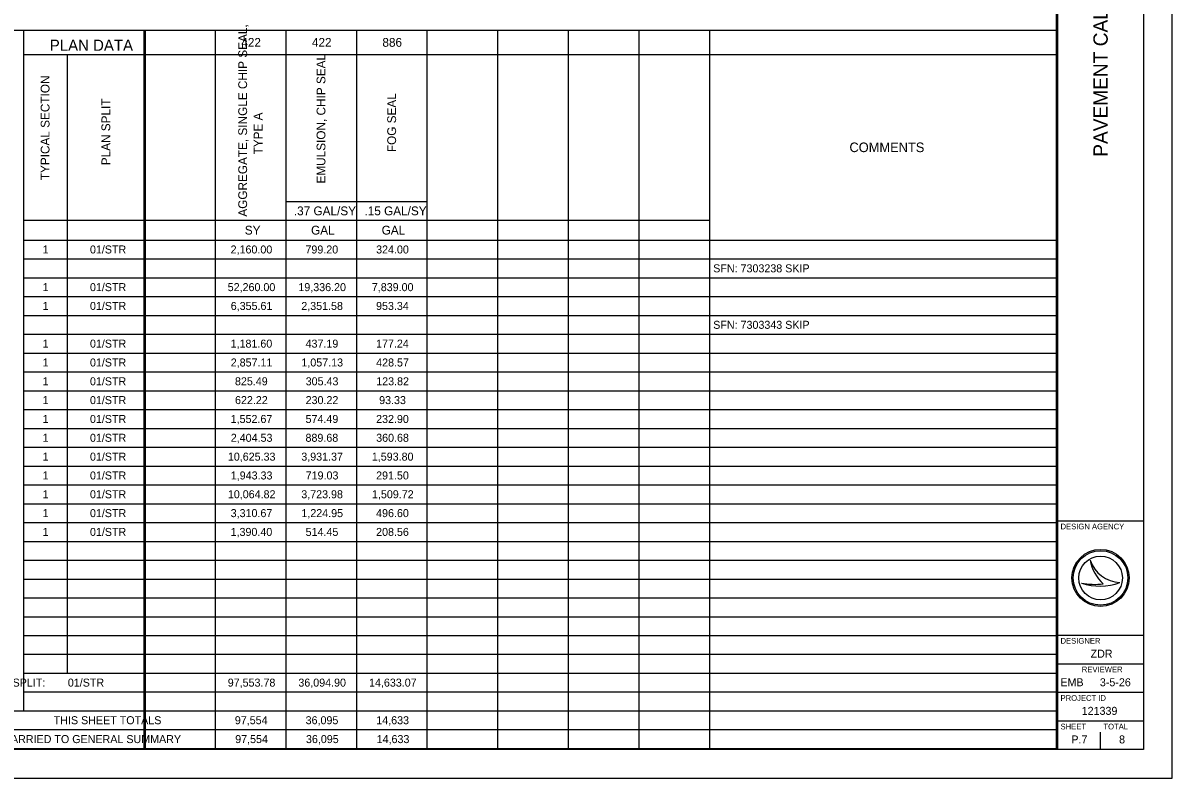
# Model space of a CAD drawing. Extents: x 0 to 34, y 0 to 31.9.
# Drawn here: x 13.9 to 34, y 0 to 13.21 of the extents above; entities that cross this region are included whole.
import ezdxf

# ---------------------------------------------------------------- set-up
doc = ezdxf.new("R2010")
doc.units = 0
for name, color, linetype in [('SH_Border', 7, 'Continuous'), ('SH_Cut_Line', 7, 'Continuous'), ('SH_Data', 7, 'Continuous'), ('SH_Text', 7, 'Continuous')]:
    doc.layers.add(name, color=color, linetype=linetype)

msp = doc.modelspace()

# ---------------------------------------------------------------- linework, layer by layer
at = {"layer": 'SH_Border'}
for p, q in [((32, 0.5), (32, 21.5)), ((32, 4.5), (33.5, 4.5)), ((32, 2.5), (33.5, 2.5)), ((32, 2), (33.5, 2)), ((32, 1.5), (33.5, 1.5)), ((32, 1), (33.5, 1))]:
    msp.add_line(p, q, dxfattribs=at)
msp.add_lwpolyline([(1.5, 21.5), (33.5, 21.5), (33.5, 0.5), (1.5, 0.5)], close=True, dxfattribs=at)
at = {"layer": 'SH_Cut_Line'}
msp.add_lwpolyline([(0, 0), (34, 0), (34, 22), (0, 22)], close=True, dxfattribs=at)
at = {"layer": 'SH_Data'}
for p, q in [((32.567, 3.81), (32.567, 3.81)), ((32.75, 3.5), (32.75, 3.5)), ((33.087, 3.419), (33.087, 3.419)), ((32.417, 3.41), (32.417, 3.41)), ((32.375, 0.675), (32.375, 0.675)), ((32.75, 0.5), (32.75, 0.8))]:
    msp.add_line(p, q, dxfattribs=at)
for radius in [0.5, 0.477, 0.477, 0.382]:
    msp.add_circle((32.75, 3.5), radius, dxfattribs=at)
for centre, radius, start, end in [((33.116, 3.998), 0.58, 198.9257, 198.9319), ((33.347, 3.97), 0.796, 191.6379, 191.6421), ((33.116, 3.998), 0.58, 198.9319, 267.1657), ((33.347, 3.97), 0.796, 191.6421, 226.0947), ((32.739, 4.37), 1.013, 251.4576, 290.0832), ((32.648, 4.654), 1.266, 259.4964, 259.4995), ((32.739, 4.37), 1.013, 251.4527, 251.4576), ((32.648, 4.654), 1.266, 259.4995, 276.6672)]:
    msp.add_arc(centre, radius, start, end, dxfattribs=at)
at = {"layer": 'SH_Text'}
for p, q in [((31.971, 21.5), (31.971, 0.516)), ((9.065, 13.084), (13.913, 13.084)), ((13.891, 13.084), (16.038, 13.084)), ((13.913, 13.084), (13.913, 1.175)), ((16.016, 13.084), (31.971, 13.084)), ((16.016, 13.084), (16.016, 0.516)), ((16.038, 13.084), (16.038, 0.516)), ((17.262, 13.084), (17.262, 0.516)), ((18.498, 13.084), (18.498, 0.516)), ((19.733, 13.084), (19.733, 0.516)), ((20.968, 13.084), (20.968, 0.516)), ((22.204, 13.084), (22.204, 0.516)), ((23.439, 13.084), (23.439, 0.516)), ((24.674, 13.084), (24.674, 0.516)), ((25.909, 13.084), (25.909, 0.516)), ((13.913, 12.655), (16.016, 12.655)), ((14.676, 12.655), (14.676, 1.834)), ((16.038, 12.655), (31.971, 12.655)), ((18.498, 10.086), (20.968, 10.086)), ((13.913, 9.756), (16.016, 9.756)), ((16.038, 9.756), (25.909, 9.756)), ((13.913, 9.411), (16.016, 9.411)), ((16.038, 9.411), (31.971, 9.411)), ((13.913, 9.081), (16.016, 9.081)), ((16.038, 9.081), (31.971, 9.081)), ((13.913, 8.752), (16.016, 8.752)), ((16.038, 8.752), (31.971, 8.752)), ((13.913, 8.422), (16.016, 8.422)), ((16.038, 8.422), (31.971, 8.422)), ((13.913, 8.093), (16.016, 8.093)), ((16.038, 8.093), (31.971, 8.093)), ((13.913, 7.764), (16.016, 7.764)), ((16.038, 7.764), (31.971, 7.764)), ((13.913, 7.434), (16.016, 7.434)), ((16.038, 7.434), (31.971, 7.434)), ((13.913, 7.105), (16.016, 7.105)), ((16.038, 7.105), (31.971, 7.105)), ((13.913, 6.775), (16.016, 6.775)), ((16.038, 6.775), (31.971, 6.775)), ((13.913, 6.446), (16.016, 6.446)), ((16.038, 6.446), (31.971, 6.446)), ((13.913, 6.116), (16.016, 6.116)), ((16.038, 6.116), (31.971, 6.116)), ((13.913, 5.787), (16.016, 5.787)), ((16.038, 5.787), (31.971, 5.787)), ((13.913, 5.458), (16.016, 5.458)), ((16.038, 5.458), (31.971, 5.458)), ((13.913, 5.128), (16.016, 5.128)), ((16.038, 5.128), (31.971, 5.128)), ((13.913, 4.799), (16.016, 4.799)), ((16.038, 4.799), (31.971, 4.799)), ((13.913, 4.469), (16.016, 4.469)), ((16.038, 4.469), (31.971, 4.469)), ((13.913, 4.14), (16.016, 4.14)), ((16.038, 4.14), (31.971, 4.14)), ((13.913, 3.811), (16.016, 3.811)), ((16.038, 3.811), (31.971, 3.811)), ((13.913, 3.481), (16.016, 3.481)), ((16.038, 3.481), (31.971, 3.481)), ((13.913, 3.152), (16.016, 3.152)), ((16.038, 3.152), (31.971, 3.152)), ((13.913, 2.822), (16.016, 2.822)), ((16.038, 2.822), (31.971, 2.822)), ((13.913, 2.493), (16.016, 2.493)), ((16.038, 2.493), (31.971, 2.493)), ((13.913, 2.164), (16.016, 2.164)), ((16.038, 2.164), (31.971, 2.164)), ((13.913, 1.834), (16.016, 1.834)), ((16.038, 1.834), (31.971, 1.834)), ((13.913, 1.505), (16.016, 1.505)), ((16.038, 1.505), (31.971, 1.505)), ((1.5, 1.175), (13.913, 1.175)), ((13.891, 1.175), (16.016, 1.175)), ((16.038, 1.175), (31.971, 1.175)), ((1.5, 0.846), (16.016, 0.846)), ((16.038, 0.846), (31.971, 0.846)), ((1.5, 0.516), (16.038, 0.516)), ((16.016, 0.516), (31.971, 0.516))]:
    msp.add_line(p, q, dxfattribs=at)

# ---------------------------------------------------------------- texts
at = {"layer": 'SH_Data'}
msp.add_text('PAVEMENT CALCULATIONS', height=0.25, rotation=90, dxfattribs=at).set_placement((32.875, 10.868))
for s, height, p in [('DESIGN AGENCY', 0.1, (32.05, 4.35)), ('DESIGNER', 0.1, (32.05, 2.35)), ('ZDR', 0.14, (32.575, 2.105)), ('REVIEWER', 0.1, (32.422, 1.85)), ('EMB', 0.14, (32.047, 1.605)), ('3-5-26', 0.14, (32.738, 1.605)), ('PROJECT ID', 0.1, (32.05, 1.35)), ('121339', 0.14, (32.42, 1.105)), ('SHEET', 0.1, (32.05, 0.85)), ('TOTAL', 0.1, (32.8, 0.85)), ('P.7', 0.14, (32.239, 0.605)), ('8', 0.14, (33.074, 0.605))]:
    msp.add_text(s, height=height, dxfattribs=at).set_placement(p)
at = {"layer": 'SH_Text'}
for s, p in [('AGGREGATE, SINGLE CHIP SEAL, ', (17.822, 9.82)), ('EMULSION, CHIP SEAL', (19.192, 10.4)), ('TYPICAL SECTION', (14.366, 10.458)), ('PLAN SPLIT', (15.429, 10.72)), ('FOG SEAL', (20.428, 10.949)), ('TYPE A', (18.092, 10.909))]:
    msp.add_text(s, height=0.154, rotation=90, dxfattribs=at).set_placement(p)
for s, height, p in [('PLAN DATA', 0.196, (14.371, 12.721)), ('422', 0.154, (17.721, 12.792)), ('422', 0.154, (18.956, 12.792)), ('886', 0.154, (20.189, 12.792)), ('COMMENTS', 0.168, (28.358, 10.949)), ('.37 GAL/SY', 0.154, (18.64, 9.844)), ('.15 GAL/SY', 0.154, (19.875, 9.844)), ('SY', 0.154, (17.782, 9.507)), ('GAL', 0.154, (18.941, 9.507)), ('GAL', 0.154, (20.176, 9.507)), ('1', 0.14, (14.245, 9.176)), ('01/STR', 0.14, (15.074, 9.176)), ('2,160.00', 0.14, (17.534, 9.176)), ('799.20', 0.14, (18.843, 9.176)), ('324.00', 0.14, (20.079, 9.176)), ('SFN: 7303238 SKIP', 0.14, (25.975, 8.846)), ('1', 0.14, (14.245, 8.517)), ('01/STR', 0.14, (15.074, 8.517)), ('52,260.00', 0.14, (17.483, 8.517)), ('19,336.20', 0.14, (18.719, 8.517)), ('7,839.00', 0.14, (20.004, 8.517)), ('1', 0.14, (14.245, 8.188)), ('01/STR', 0.14, (15.074, 8.188)), ('6,355.61', 0.14, (17.536, 8.188)), ('2,351.58', 0.14, (18.77, 8.188)), ('953.34', 0.14, (20.078, 8.188)), ('SFN: 7303343 SKIP', 0.14, (25.975, 7.858)), ('1', 0.14, (14.245, 7.529)), ('01/STR', 0.14, (15.074, 7.529)), ('1,181.60', 0.14, (17.534, 7.529)), ('437.19', 0.14, (18.845, 7.529)), ('177.24', 0.14, (20.078, 7.529)), ('1', 0.14, (14.245, 7.199)), ('01/STR', 0.14, (15.074, 7.199)), ('2,857.11', 0.14, (17.536, 7.199)), ('1,057.13', 0.14, (18.772, 7.199)), ('428.57', 0.14, (20.08, 7.199)), ('1', 0.14, (14.245, 6.87)), ('01/STR', 0.14, (15.074, 6.87)), ('825.49', 0.14, (17.61, 6.87)), ('305.43', 0.14, (18.847, 6.87)), ('123.82', 0.14, (20.081, 6.87)), ('1', 0.14, (14.245, 6.541)), ('01/STR', 0.14, (15.074, 6.541)), ('622.22', 0.14, (17.611, 6.541)), ('230.22', 0.14, (18.846, 6.541)), ('93.33', 0.14, (20.132, 6.541)), ('1', 0.14, (14.245, 6.211)), ('01/STR', 0.14, (15.074, 6.211)), ('1,552.67', 0.14, (17.535, 6.211)), ('574.49', 0.14, (18.845, 6.211)), ('232.90', 0.14, (20.079, 6.211)), ('1', 0.14, (14.245, 5.882)), ('01/STR', 0.14, (15.074, 5.882)), ('2,404.53', 0.14, (17.537, 5.882)), ('889.68', 0.14, (18.844, 5.882)), ('360.68', 0.14, (20.08, 5.882)), ('1', 0.14, (14.245, 5.552)), ('01/STR', 0.14, (15.074, 5.552)), ('10,625.33', 0.14, (17.486, 5.552)), ('3,931.37', 0.14, (18.77, 5.552)), ('1,593.80', 0.14, (20.004, 5.552)), ('1', 0.14, (14.245, 5.223)), ('01/STR', 0.14, (15.074, 5.223)), ('1,943.33', 0.14, (17.537, 5.223)), ('719.03', 0.14, (18.847, 5.223)), ('291.50', 0.14, (20.079, 5.223)), ('1', 0.14, (14.245, 4.894)), ('01/STR', 0.14, (15.074, 4.894)), ('10,064.82', 0.14, (17.486, 4.894)), ('3,723.98', 0.14, (18.77, 4.894)), ('1,509.72', 0.14, (20.007, 4.894)), ('1', 0.14, (14.245, 4.564)), ('01/STR', 0.14, (15.074, 4.564)), ('3,310.67', 0.14, (17.535, 4.564)), ('1,224.95', 0.14, (18.772, 4.564)), ('496.60', 0.14, (20.079, 4.564)), ('1', 0.14, (14.245, 4.235)), ('01/STR', 0.14, (15.074, 4.235)), ('1,390.40', 0.14, (17.534, 4.235)), ('514.45', 0.14, (18.846, 4.235)), ('208.56', 0.14, (20.079, 4.235)), ('SUBTOTAL FOR PLAN SPLIT:', 0.14, (11.692, 1.599)), ('01/STR', 0.14, (14.687, 1.599)), ('97,553.78', 0.14, (17.484, 1.599)), ('36,094.90', 0.14, (18.719, 1.599)), ('14,633.07', 0.14, (19.955, 1.599)), ('THIS SHEET TOTALS', 0.14, (14.44, 0.941)), ('97,554', 0.14, (17.608, 0.941)), ('36,095', 0.14, (18.846, 0.941)), ('14,633', 0.14, (20.082, 0.941)), ('TOTALS CARRIED TO GENERAL SUMMARY', 0.14, (12.777, 0.611)), ('97,554', 0.14, (17.614, 0.611)), ('36,095', 0.14, (18.852, 0.611)), ('14,633', 0.14, (20.088, 0.611))]:
    msp.add_text(s, height=height, dxfattribs=at).set_placement(p)

doc.saveas('drawing.dxf')
